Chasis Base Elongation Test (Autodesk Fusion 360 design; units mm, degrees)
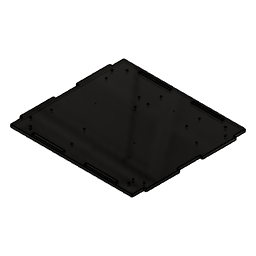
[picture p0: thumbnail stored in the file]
sketch "Sketch1" plane through (0, 0, 0) normal (0, 0, 1) x axis (1, 0, 0)
  line L1 (105, 0) -> (105, 170)
  line L2 (270, 85) -> (105, 85)
  line L3 (187.5, 0) -> (187.5, 170)
  line L4 (270, 170) -> (270, 0)
  line L5 (270, 0) -> (105, 0)
  line L6 (105, 170) -> (270, 170)
  line L7 (214, 237) -> (105, 237)
  line L8 (214, 185) -> (214, 237)
  line L9 (105, 185) -> (214, 185)
  line L10 (105, 237) -> (105, 185)
  line L11 (214, 237) -> (105, 185)
  line L12 (214, 185) -> (105, 237)
  line L13 (110.5, 194.5) -> (208.5, 194.5)
  line L14 (110.5, 227.5) -> (110.5, 194.5)
  line L15 (208.5, 227.5) -> (110.5, 227.5)
  line L16 (208.5, 194.5) -> (208.5, 227.5)
  line L17 (110.5, 227.5) -> (208.5, 194.5)
  line L18 (208.5, 227.5) -> (110.5, 194.5)
  line L19 (159.5, 237) -> (159.5, 185)
  line L20 (0, -15) -> (0, 0)
  line L21 (-15, -15) -> (0, -15)
  line L22 (285, 170) -> (270, 170)
  line L23 (214, 252) -> (214, 237)
  line L24 (285, 252) -> (214, 252)
  line L25 (285, -15) -> (-15, -15)
  line L26 (285, 252) -> (285, -15)
  line L27 (-15, 252) -> (285, 252)
  line L28 (-15, -15) -> (-15, 252)
  line L29 (4.75, 385) -> (24.75, 385)
  line L30 (0, 385) -> (24.75, 385)
  line L31 (11.6375, 396.25) -> (39.75, 396.25)
  line L32 (9.75, 373.75) -> (9.75, 396.25)
  line L33 (39.75, 373.75) -> (11.6375, 373.75)
  line L34 (39.75, 396.25) -> (39.75, 373.75)
  line L35 (9.75, 373.75) -> (39.75, 396.25)
  line L36 (39.75, 373.75) -> (9.75, 396.25)
  line L37 (1.4898, 388.4545) -> (8.3773, 394.9545)
  line L38 (8.3773, 375.0455) -> (1.4898, 381.5455)
  line L39 (-15, -15) -> (285, 252)
  line L40 (285, -15) -> (-15, 252)
  line L41 (-26, 263) -> (296, 263)
  line L42 (-26, -26) -> (-26, 263)
  line L43 (296, -26) -> (-26, -26)
  line L44 (296, 263) -> (296, -26)
  line L45 (-26, -26) -> (296, 263)
  line L46 (296, -26) -> (-26, 263)
  line L47 (15.3041, 394.5767) -> (10.5355, 389.7534)
  line L48 (24.75, 395.23) -> (16.8686, 395.23)
  line L49 (24.75, 374.77) -> (14.3, 374.77)
  line L50 (39.6, 388.2067) -> (39.6, 379.17)
  line L51 (24.75, 374.77) -> (35.2, 374.77)
  line L52 (9.9, 388.2067) -> (9.9, 379.17)
  line L53 (34.1959, 394.5767) -> (38.9645, 389.7534)
  line L54 (24.75, 395.23) -> (32.6314, 395.23)
  line L55 (24.75, 374.77) -> (24.75, 395.23)
  line L56 (9.9, 385) -> (24.75, 385)
  line L57 (39.6, 385) -> (24.75, 385)
  line L58 (108, -15) -> (28, -15)
  line L59 (108, -21) -> (108, -15)
  line L60 (28, -21) -> (108, -21)
  line L61 (28, -15) -> (28, -21)
  line L62 (135, 263) -> (135, -26)
  line L63 (162, -15) -> (242, -15)
  line L64 (242, -21) -> (162, -21)
  line L65 (242, -15) -> (242, -21)
  line L66 (162, -21) -> (162, -15)
  line L67 (296, 118.5) -> (-26, 118.5)
  line L68 (162, 258) -> (162, 252)
  line L69 (242, 258) -> (162, 258)
  line L70 (242, 252) -> (242, 258)
  line L71 (108, 258) -> (108, 252)
  line L72 (28, 258) -> (108, 258)
  line L73 (108, 252) -> (28, 252)
  line L74 (162, 252) -> (242, 252)
  line L75 (28, 252) -> (28, 258)
  line L76 (-20, 4) -> (-20, -26)
  line L77 (-26, 4) -> (-20, 4)
  line L78 (-20, 233) -> (-20, 263)
  line L79 (-26, 233) -> (-20, 233)
  line L80 (-26, 233) -> (-26, 4)
  line L81 (290, 4) -> (290, -26)
  line L82 (296, 4) -> (290, 4)
  line L83 (296, 233) -> (296, 4)
  line L84 (296, 233) -> (290, 233)
  line L85 (290, 233) -> (290, 263)
  line L86 (290, 263) -> (-20, 263)
  line L87 (290, -26) -> (-20, -26)
  line L88 (4.75, 385) -> (44.75, 385)
  line L89 (290, 460) -> (-20, 460)
  line L90 (28, 304) -> (28, 310)
  line L91 (108, 304) -> (28, 304)
  line L92 (108, 310) -> (108, 304)
  line L93 (162, 304) -> (162, 310)
  line L94 (242, 304) -> (162, 304)
  line L95 (242, 310) -> (242, 304)
  line L96 (242, 310) -> (290, 310)
  line L97 (108, 310) -> (162, 310)
  line L98 (28, 310) -> (-20, 310)
  line L99 (-20, 340) -> (-20, 310)
  line L100 (-26, 340) -> (-20, 340)
  line L101 (-26, 430) -> (-26, 340)
  line L102 (-20, 430) -> (-26, 430)
  line L103 (-20, 430) -> (-20, 460)
  line L104 (-20, 385) -> (290, 385)
  line L105 (28, 460) -> (-20, 460)
  line L106 (242, 460) -> (242, 466)
  line L107 (28, 466) -> (28, 460)
  line L108 (242, 466) -> (162, 466)
  line L109 (242, 460) -> (290, 460)
  line L110 (108, 460) -> (108, 466)
  line L111 (108, 460) -> (162, 460)
  line L112 (108, 466) -> (28, 466)
  line L113 (162, 466) -> (162, 460)
  line L114 (135, 460) -> (135, 385)
  line L115 (296, 430) -> (296, 340)
  line L116 (290, 430) -> (290, 460)
  line L117 (290, 340) -> (290, 310)
  line L118 (296, 340) -> (290, 340)
  line L119 (290, 430) -> (296, 430)
  line L120 (0, 412.9257) -> (0, 385)
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  point P9 (105, 0)
  point P32 (105, 0)
  point P31 (105, 85)
  point P30 (270, 85)
  point P28 (187.5, 170)
  point P25 (187.5, 0)
  point P41 (159.5, 211)
  point P39 (110.5, 227.5)
  point P42 (110.5, 227.5)
  point P40 (208.5, 227.5)
  point P43 (208.5, 227.5)
  point P38 (110.5, 194.5)
  point P44 (110.5, 194.5)
  point P37 (208.5, 194.5)
  point P45 (208.5, 194.5)
  point P46 (159.5, 185)
  point P47 (159.5, 237)
  point P61 (4.75, 385)
  point P62 (4.75, 385)
  point P69 (24.75, 385)
  point P60 (24.75, 385)
  point P66 (9.75, 396.25)
  point P67 (9.75, 373.75)
  point P84 (135, 118.5)
  point P107 (24.75, 385)
  point P108 (9.9, 385)
  point P109 (39.6, 385)
  point P110 (28, -15)
  point P114 (135, -26)
  point P115 (135, 263)
  point P116 (242, -15)
  point P111 (108, -15)
  point P117 (162, -15)
  point P112 (108, -21)
  point P118 (162, -21)
  point P113 (28, -21)
  point P119 (242, -21)
  point P120 (-26, 118.5)
  point P121 (296, 118.5)
  point P125 (242, 252)
  point P122 (162, 252)
  point P123 (162, 258)
  point P124 (242, 258)
  point P130 (-20, -26)
  point P132 (-26, 4)
  point P133 (-20, 263)
  point P131 (-20, 4)
  point P134 (-20, 233)
  point P135 (-26, 233)
  point P136 (290, -26)
  point P137 (290, 4)
  point P138 (296, 4)
  point P141 (290, 263)
  point P140 (290, 233)
  point P139 (296, 233)
  point P79 (44.75, 385)
  point P142 (44.75, 385)
  point P143 (4.75, 385)
  point P144 (-20, 310)
  point P170 (-20, 460)
  point P145 (290, 310)
  point P171 (290, 460)
  point P148 (28, 310)
  point P168 (28, 460)
  point P149 (28, 304)
  point P169 (28, 466)
  point P150 (108, 304)
  point P162 (108, 466)
  point P151 (108, 310)
  point P167 (108, 460)
  point P152 (162, 310)
  point P165 (162, 460)
  point P153 (162, 304)
  point P164 (162, 466)
  point P154 (242, 304)
  point P163 (242, 466)
  point P155 (242, 310)
  point P166 (242, 460)
  point P172 (135, 385)
  point P173 (135, 460)
  point P178 (290, 310)
  point P146 (-20, 460)
  point P176 (290, 460)
  point P156 (-20, 340)
  point P179 (290, 340)
  point P157 (-26, 340)
  point P174 (296, 340)
  point P158 (-26, 430)
  point P175 (296, 430)
  point P159 (-20, 430)
  point P177 (290, 430)
  point P180 (0, 385)
  point P203 (-445.6879, 118.6195)
  point P208 (-445.6879, 118.6195)
  point P329 (-3, 53)
  point P332 (-3, 53)
  point P339 (-3, 53)
  point P340 (108, -18)
  point P341 (162, -18)
  point P20 (266, 4)
  point P349 (266, 4)
  point P351 (258, 9)
  point P353 (258, 9)
  point P21 (109, 4)
  point P354 (109, 4)
  point P356 (101, 9)
  point P358 (101, 9)
  point P48 (109, 166)
  point P359 (109, 166)
  point P361 (101, 171)
  point P363 (101, 171)
  point P49 (266, 166)
  point P364 (266, 166)
  point P366 (258, 171)
  point P368 (258, 171)
  point P17 (270, 0)
  point P18 (270, 170)
  point P19 (215, 4)
  point P22 (165, 4)
  point P26 (109, 166)
  point P29 (160, 166)
  point P12 (215, 166)
  point P27 (266, 166)
  point P15 (266, 70)
  point P7 (266, 110)
  point P6 (109, 60)
  point P8 (109, 100)
  point P23 (190, 40)
  point P24 (190, 74)
  point P10 (259, 15)
  point P14 (259, 30)
  point P11 (259, 45)
  point P13 (259, 60)
  point P2 (259, 159)
  point P3 (259, 144)
  point P4 (115, 145)
  point P5 (115, 130)
  point P33 (105, 237)
  point P34 (214, 237)
  point P36 (105, 185)
  point P53 (0, -15)
  point P54 (-15, -15)
  point P55 (285, 170)
  point P56 (214, 252)
  point P63 (0, 385)
  point P68 (39.75, 373.75)
  point P82 (-26, -26)
  point P83 (296, -26)
  point P81 (-26, 263)
  point P59 (-15, 252)
  point P102 (9.9, 379.17)
  point P106 (9.9, 388.2067)
  point P87 (16.8686, 395.23)
  point P99 (24.75, 395.23)
  point P85 (24.75, 374.77)
  point P101 (14.3, 374.77)
  point P183 (-230.6879, -25.8805)
  point P184 (-260.6879, -25.8805)
  point P186 (-260.6879, 3.9615)
  point P187 (-266.6879, 3.9615)
  point P188 (-260.6879, 232.9615)
  point P189 (-266.6879, 232.9615)
  point P185 (-260.6879, 263.1195)
  point P190 (-410.6879, 263.1195)
  point P191 (-410.6879, -25.8805)
  point P200 (-430.6879, -25.8805)
  point P202 (-430.6879, 118.6195)
  point P205 (-458.1879, 58.6195)
  point P206 (-458.1879, 178.6195)
  point P209 (-458.1879, 118.6195)
  point P210 (-478.1879, 118.6195)
  point P213 (-478.1879, 45.3383)
  point P214 (-478.1879, 15.3383)
  point P219 (-260.6879, 252)
  point P220 (-290.6879, 252)
  point P222 (-410.6879, 252)
  point P223 (-380.6879, 252)
  point P224 (-290.6879, 252)
  point P226 (-380.6879, 258)
  point P207 (-433.1879, 178.6195)
  point P182 (-230.6879, 263.1195)
  point P275 (590, 237)
  point P277 (490, 237)
  point P278 (490, 197)
  point P299 (540, 237)
  point P300 (590, 187)
  point P333 (87, 53)
  point P325 (-3, 203)
  point P350 (258, 4)
  point P352 (266, 9)
  point P355 (101, 4)
  point P357 (109, 9)
  point P365 (258, 166)
  point P367 (266, 171)
  horizontal L5
  vertical L4
  horizontal L6
  vertical L1
  coincident P9 P32
  midpoint P31 L1
  midpoint P30 L4
  midpoint P28 L6
  midpoint P25 L5
  horizontal L7
  vertical L8
  horizontal L9
  vertical L10
  horizontal L13
  perpendicular L13 L14
  parallel L13 L15
  parallel L14 L16
  coincident L17 P41
  coincident L18 P41
  midpoint L12 P41
  coincident P39 P42
  coincident P40 P43
  coincident P38 P44
  coincident P37 P45
  midpoint L9 P46
  midpoint L7 P47
  perpendicular L20 L21
  perpendicular L4 L22
  perpendicular L7 L23
  perpendicular L4 L24
  horizontal L25
  vertical L26
  horizontal L27
  vertical L28
  coincident P61 P62
  parallel L29 L30
  horizontal L31
  perpendicular L31 L32
  parallel L31 L33
  parallel L32 L34
  coincident L35 P69
  coincident L36 P69
  coincident P60 P69
  coincident P66 L37
  coincident P66 L31
  coincident P67 L38
  coincident P67 L33
  horizontal L41
  perpendicular L41 L42
  parallel L41 L43
  parallel L42 L44
  coincident L45 P84
  coincident L46 P84
  midpoint L40 P84
  parallel L48 L54
  parallel L51 L54
  parallel L49 L51
  equal L50 L52
  equal L47 L53
  equal L48 L54
  equal L49 L51
  collinear L48 L54
  collinear L49 L51
  perpendicular L49 L55
  midpoint L55 P107
  coincident L52 P108
  perpendicular L52 L56
  coincident L50 P109
  equal L56 L57
  parallel L50 L55
  horizontal L58
  vertical L59
  horizontal L60
  vertical L61
  coincident L25 P110
  midpoint L43 P114
  midpoint L41 P115
  symmetric P110 L62 P116
  symmetric P111 L62 P117
  symmetric P112 L62 P118
  symmetric P113 L62 P119
  midpoint L42 P120
  midpoint L44 P121
  symmetric P116 L67 P125
  symmetric P117 L67 P122
  symmetric P118 L67 P123
  symmetric P119 L67 P124
  coincident L43 P130
  perpendicular L25 L76
  coincident L42 P132
  perpendicular L42 L77
  symmetric L67 P130 P133
  symmetric L67 P131 P134
  symmetric L67 P132 P135
  symmetric L62 P130 P136
  symmetric L62 P131 P137
  symmetric L62 P132 P138
  symmetric L62 P133 P141
  symmetric L62 P134 P140
  symmetric L62 P135 P139
  coincident P79 P142
  coincident P62 P143
  parallel L29 L88
  equal L37 L38
  perpendicular L71 L91
  perpendicular L70 L94
  perpendicular L99 L100
  perpendicular L100 L101
  symmetric P144 L104 P170
  symmetric P145 L104 P171
  symmetric P148 L104 P168
  symmetric P149 L104 P169
  symmetric P150 L104 P162
  symmetric P151 L104 P167
  symmetric P152 L104 P165
  symmetric P153 L104 P164
  symmetric P154 L104 P163
  symmetric P155 L104 P166
  midpoint L104 P172
  midpoint L111 P173
  symmetric P144 L114 P178
  symmetric P146 L114 P176
  symmetric P156 L114 P179
  symmetric P157 L114 P174
  symmetric P158 L114 P175
  symmetric P159 L114 P177
  coincident L104 P180
  perpendicular L104 L120
  coincident P203 P208
  coincident P329 P332
  coincident P329 P339
  collinear L1 L10
  midpoint L59 P340
  midpoint L66 P341
  coincident P20 P349
  coincident P351 P353
  coincident P21 P354
  coincident P356 P358
  coincident P48 P359
  coincident P361 P363
  coincident P49 P364
  coincident P366 P368
  dimension "d10" distance P17 P18 = 170
  dimension "d11" distance P17 P32 = 165
  dimension "d12" diameter = 3
  dimension "d13" distance P20 L5 = 4
  dimension "d14" distance P20 L4 = 4
  dimension "d15" diameter = 3
  dimension "d16" distance P19 P20 = 51
  dimension "d17" diameter = 3
  dimension "d18" distance P19 P22 = 50
  dimension "d19" diameter = 3
  dimension "d20" distance P21 P22 = 56
  dimension "d21" distance P19 L5 = 4
  dimension "d22" distance P22 L5 = 4
  dimension "d23" distance P21 L5 = 4
  dimension "d24" distance P26 P29 = 51
  dimension "d25" diameter = 3
  dimension "d26" distance P12 P27 = 51
  dimension "d27" diameter = 3
  dimension "d28" distance P15 P20 = 66
  dimension "d29" diameter = 3
  dimension "d30" distance P7 P15 = 40
  dimension "d31" diameter = 3
  dimension "d32" distance P6 P21 = 56
  dimension "d33" diameter = 3
  dimension "d34" distance P6 P8 = 40
  dimension "d35" diameter = 3
  dimension "d36" distance P23 L4 = 80
  dimension "d37" distance P23 L5 = 40
  dimension "d38" diameter = 3
  dimension "d39" distance P23 P24 = 34
  dimension "d40" diameter = 6
  dimension "d41" distance P10 L5 = 15
  dimension "d42" distance P10 L4 = 11
  dimension "d43" diameter = 6
  dimension "d44" diameter = 6
  dimension "d45" diameter = 6
  dimension "d46" distance P10 P14 = 15
  dimension "d47" distance P11 P14 = 15
  dimension "d48" distance P11 P13 = 15
  dimension "d49" diameter = 6
  dimension "d50" distance P2 L6 = 11
  dimension "d51" distance P2 L4 = 11
  dimension "d52" diameter = 6
  dimension "d53" distance P2 P3 = 15
  dimension "d54" diameter = 6
  dimension "d55" distance P4 L6 = 25
  dimension "d56" distance P4 L1 = 10
  dimension "d57" diameter = 6
  dimension "d58" distance P4 P5 = 15
  dimension "d59" distance P33 P34 = 109
  dimension "d60" distance P33 P36 = 52
  dimension "d61" distance P39 P40 = 98
  dimension "d62" distance P38 P39 = 33
  dimension "d63" diameter = 3.5
  dimension "d64" diameter = 3.5
  dimension "d65" diameter = 3.5
  dimension "d66" diameter = 3.5
  dimension "d74" diameter = 3.5
  dimension "d75" diameter = 3.5
  dimension "d76" diameter = 3.5
  dimension "d77" diameter = 3.5
  dimension "d78" distance L6 L9 = 15
  dimension "d81" distance P53 P54 = 15
  dimension "d82" distance P18 P55 = 15
  dimension "d83" distance P34 P56 = 15
  dimension "d86" distance P60 P61 = 20
  dimension "d87" diameter = 4
  dimension "d88" distance P60 P63 = 24.75 (= "( 49.5 / 2 ) * 1 mm")
  dimension "d89" distance P67 P68 = 30
  dimension "d90" distance P66 P67 = 22.5
  dimension "d91" radius = 4.75 (= "( 9.5 / 2 ) * 1 mm")
  dimension "d94" radius = 4.75 (= "( 9.5 / 2 ) * 1 mm")
  dimension "d98" distance P82 P83 = 322
  dimension "d99" distance P81 P82 = 289 (= "267 mm + ( 11 * 2 ) * 1 mm")
  dimension "d100" distance P54 P59 = 267
  dimension "d144" radius = 2.2
  dimension "d145" radius = 4.4
  dimension "d146" distance L48 L49 = 20.46
  dimension "d147" distance P102 P106 = 9.0367
  dimension "d148" distance L50 L52 = 29.7
  dimension "d149" distance P87 P99 = 7.8814
  dimension "d150" distance P85 P101 = 10.45
  dimension "d151" distance L31 L54 = 1.02
  dimension "d152" distance P62 L52 = 5.15
  dimension "d154" distance P110 P111 = 80
  dimension "d155" distance P110 P113 = 6
  dimension "d156" distance L42 L61 = 54
  dimension "d157" distance L28 L42 = 11
  dimension "d158" distance P130 P131 = 30
  dimension "d159" distance L42 L76 = 6
  dimension "d161" distance P62 P79 = 40
  dimension "d162" distance P144 P146 = 150
  dimension "d163" distance P148 P149 = 6
  dimension "d164" distance P144 P156 = 30
  dimension "d165" distance P156 P157 = 6
  dimension "d167" distance P157 P158 = 90
  dimension "d168" distance P183 P184 = 30
  dimension "d169" distance P186 P187 = 6
  dimension "d170" distance P188 P189 = 6
  dimension "d171" distance P185 P190 = 150
  dimension "d172" distance P191 P200 = 20
  dimension "d173" distance P202 P203 = 15
  dimension "d174" distance P205 P206 = 120
  dimension "d175" distance P209 P210 = 20
  dimension "d176" distance P213 P214 = 30
  dimension "d177" distance P219 P220 = 30
  dimension "d178" distance P222 P223 = 30
  dimension "d179" distance P223 P224 = 90
  dimension "d180" distance P223 P226 = 6
  dimension "d181" distance P206 P207 = 25
  dimension "d184" distance P182 P183 = 289
  dimension "d185" distance P275 P277 = 100
  dimension "d186" distance P277 P278 = 40
  dimension "d187" distance P275 P299 = 50
  dimension "d188" distance P275 P300 = 50
  dimension "d189" diameter = 3.5
  dimension "d190" distance = 3
  dimension "d191" distance = 3
  dimension "d192" diameter = 3.5
  dimension "d193" distance = 4
  dimension "d194" distance P329 P333 = 90
  dimension "d195" distance P325 P329 = 150
  dimension "d196" radius = 5
  dimension "d197" radius = 5
  dimension "d198" radius = 5
  dimension "d199" radius = 5
  dimension "d200" diameter = 3
  dimension "d201" distance = 5
  dimension "d202" distance = 3
  dimension "d203" diameter = 3.5
  dimension "d204" diameter = 3.5
  dimension "d205" diameter = 3.5
  dimension "d206" diameter = 3.5
  dimension "d207" distance = 60
  dimension "d208" distance = 23
  dimension "d212" diameter = 3.05
  dimension "d213" diameter = 3.05
  dimension "d214" diameter = 3.05
  dimension "d236" distance P349 P350 = 8
  dimension "d237" distance P349 P352 = 5
  dimension "d238" diameter = 3.5
  dimension "d239" distance P354 P355 = 8
  dimension "d240" distance P354 P357 = 5
  dimension "d241" diameter = 3.5
  dimension "d242" diameter = 3.5
  dimension "d243" distance P364 P365 = 8
  dimension "d244" distance P364 P367 = 5
  dimension "d245" diameter = 3.5
extrude "Extrude1" new body sketch "Sketch1" along normal blind 6
sketch "Sketch3" plane through (0, 0, 6) normal (0, 0, 1) x axis (-1, 0, 0)
  line L1 (-296, -4) -> (-290, -4)
  line L2 (-296, -233) -> (-296, -4)
  line L3 (-290, -233) -> (-296, -233)
  line L4 (-290, -263) -> (-290, -233)
  line L5 (20, -263) -> (-290, -263)
  line L6 (20, -233) -> (20, -263)
  line L7 (26, -233) -> (20, -233)
  line L8 (26, -4) -> (26, -233)
  line L9 (20, -4) -> (26, -4)
  line L10 (20, 26) -> (20, -4)
  line L11 (-290, 26) -> (20, 26)
  line L12 (-290, -4) -> (-290, 26)
  line L13 (-242, -252) -> (-242, -258)
  line L14 (-162, -252) -> (-242, -252)
  line L15 (-162, -258) -> (-162, -252)
  line L16 (-242, -258) -> (-162, -258)
  line L17 (-28, -258) -> (-28, -252)
  line L18 (-108, -258) -> (-28, -258)
  line L19 (-108, -252) -> (-108, -258)
  line L20 (-28, -252) -> (-108, -252)
  line L21 (-28, 21) -> (-108, 21)
  line L22 (-28, 15) -> (-28, 21)
  line L23 (-108, 15) -> (-28, 15)
  line L24 (-108, 21) -> (-108, 15)
  line L25 (-162, 15) -> (-162, 21)
  line L26 (-242, 15) -> (-162, 15)
  line L27 (-242, 21) -> (-242, 15)
  line L28 (-162, 21) -> (-242, 21)
  line L29 (-296, -148) -> (-296, -233)
  line L30 (-296, -89) -> (-296, -4)
  line L31 (-290, -89) -> (-296, -89)
  line L32 (-290, -148) -> (-296, -148)
  line L33 (-290, -148) -> (-290, -89)
  line L34 (-296, -89) -> (-296, -148)
  line L35 (-135, -29) -> (-135, 18)
  line L36 (26, -89) -> (26, -148)
  line L37 (20, -148) -> (20, -89)
  line L38 (20, -89) -> (26, -89)
  line L39 (20, -148) -> (26, -148)
  circle C1 centre (-208.5, -227.5) radius 1.75
  circle C2 centre (-110.5, -227.5) radius 1.75
  circle C3 centre (-208.5, -194.5) radius 1.75
  circle C4 centre (0, -58) radius 1.75
  circle C5 centre (0, -198) radius 1.75
  circle C6 centre (-84, -58) radius 1.75
  circle C7 centre (-84, -198) radius 1.75
  circle C8 centre (-110.5, -194.5) radius 1.75
  circle C9 centre (-258, -9) radius 1.75
  circle C10 centre (-101, -9) radius 1.75
  circle C11 centre (-101, -171) radius 1.75
  circle C12 centre (-258, -171) radius 1.75
  point P5 (-296, -233)
  point P44 (-296, -233)
  point P3 (-296, -4)
  point P46 (-296, -4)
  point P45 (-296, -148)
  point P52 (26, -148)
  point P47 (-296, -89)
  point P53 (26, -89)
  point P48 (-290, -89)
  point P54 (20, -89)
  point P49 (-290, -148)
  point P55 (20, -148)
  coincident P5 P44
  perpendicular L3 L29
  coincident P3 P46
  perpendicular L1 L30
  perpendicular L30 L31
  vertical L35
  symmetric P45 L35 P52
  symmetric P47 L35 P53
  symmetric P48 L35 P54
  symmetric P49 L35 P55
  dimension "d223" distance P44 P45 = 85
  dimension "d224" distance P46 P47 = 85
  dimension "d225" distance P47 P48 = 6
  dimension "d226" distance P45 P49 = 6
extrude "Extrude3" cut sketch "Sketch3" profile of L2 L8 L31 L32 L33 L34 L36 L37 L38 L39 against normal blind 30
sketch "Sketch4" plane through (0, 0, 6) normal (0, 0, 1) x axis (-1, 0, 0)
  line L1 (-296, -148) -> (-290, -148)
  line L2 (-296, -233) -> (-296, -148)
  line L3 (-290, -233) -> (-296, -233)
  line L4 (-290, -263) -> (-290, -233)
  line L5 (20, -263) -> (-290, -263)
  line L6 (20, -233) -> (20, -263)
  line L7 (26, -233) -> (20, -233)
  line L8 (26, -148) -> (26, -233)
  line L9 (20, -148) -> (26, -148)
  line L10 (20, -89) -> (20, -148)
  line L11 (26, -89) -> (20, -89)
  line L12 (26, -4) -> (26, -89)
  line L13 (20, -4) -> (26, -4)
  line L14 (20, 26) -> (20, -4)
  line L15 (-290, 26) -> (20, 26)
  line L16 (-290, -4) -> (-290, 26)
  line L17 (-296, -4) -> (-290, -4)
  line L18 (-296, -89) -> (-296, -4)
  line L19 (-290, -89) -> (-296, -89)
  line L20 (-290, -148) -> (-290, -89)
  line L21 (-242, -252) -> (-242, -258)
  line L22 (-162, -252) -> (-242, -252)
  line L23 (-162, -258) -> (-162, -252)
  line L24 (-242, -258) -> (-162, -258)
  line L25 (-28, -258) -> (-28, -252)
  line L26 (-108, -258) -> (-28, -258)
  line L27 (-108, -252) -> (-108, -258)
  line L28 (-28, -252) -> (-108, -252)
  line L29 (-28, 21) -> (-108, 21)
  line L30 (-28, 15) -> (-28, 21)
  line L31 (-108, 15) -> (-28, 15)
  line L32 (-108, 21) -> (-108, 15)
  line L33 (-162, 15) -> (-162, 21)
  line L34 (-242, 15) -> (-162, 15)
  line L35 (-242, 21) -> (-242, 15)
  line L36 (-162, 21) -> (-242, 21)
  line L37 (20, 15) -> (-28, 15)
  line L38 (10, 15) -> (20, 15)
  line L39 (10, -14.5) -> (10, 15)
  line L40 (20, -14.5) -> (10, -14.5)
  line L41 (20, 15) -> (20, -14.5)
  line L42 (-135, -263) -> (-135, 26)
  line L43 (-290, -118.5) -> (20, -118.5)
  line L44 (-9.5, 15) -> (20, 15)
  line L45 (-9.5, 5) -> (-9.5, 15)
  line L46 (20, 5) -> (-9.5, 5)
  line L47 (20, 15) -> (20, 5)
  circle C1 centre (-208.5, -227.5) radius 1.75
  circle C2 centre (-110.5, -227.5) radius 1.75
  circle C3 centre (-208.5, -194.5) radius 1.75
  circle C4 centre (0, -58) radius 1.75
  circle C5 centre (0, -198) radius 1.75
  circle C6 centre (-84, -58) radius 1.75
  circle C7 centre (-84, -198) radius 1.75
  circle C8 centre (-110.5, -194.5) radius 1.75
  circle C9 centre (10, -14.5) radius 2.05
  circle C10 centre (-280, -14.5) radius 2.05
  circle C11 centre (-280, -222.5) radius 2.05
  circle C12 centre (10, -222.5) radius 2.05
  circle C13 centre (-9.5, 5) radius 2.05
  circle C14 centre (-260.5, 5) radius 2.05
  circle C15 centre (-9.5, -242) radius 2.05
  circle C16 centre (-260.5, -242) radius 2.05
  circle C17 centre (-258, -9) radius 1.75
  circle C18 centre (-101, -9) radius 1.75
  circle C19 centre (-101, -171) radius 1.75
  circle C20 centre (-258, -171) radius 1.75
  point P39 (-28, 15)
  point P46 (-28, 15)
  point P47 (20, 15)
  point P49 (10, -14.5)
  point P51 (10, -14.5)
  point P52 (-135, 26)
  point P53 (-135, -263)
  point P54 (20, -118.5)
  point P55 (-290, -118.5)
  point P60 (-9.5, 5)
  point P62 (-9.5, 5)
  point P48 (10, 15)
  point P50 (20, -14.5)
  point P59 (-9.5, 15)
  point P61 (20, 5)
  coincident P39 P46
  coincident L14 P47
  perpendicular L14 L37
  horizontal L38
  vertical L39
  horizontal L40
  vertical L41
  coincident P49 P51
  midpoint L15 P52
  midpoint L5 P53
  midpoint L10 P54
  midpoint L20 P55
  symmetric C9 L42 C10
  symmetric C9 L43 C12
  symmetric L43 C10 C11
  horizontal L44
  vertical L45
  horizontal L46
  vertical L47
  coincident P60 P62
  symmetric L42 C13 C14
  symmetric L43 C13 C15
  symmetric L43 C14 C16
  dimension "d229" distance P47 P48 = 10
  dimension "d230" distance P47 P50 = 29.5 (= "27 mm + 2.5 mm")
  dimension "d231" diameter C9 = 4.1
  dimension "d233" distance P47 P59 = 29.5
  dimension "d234" distance P47 P61 = 10
  dimension "d235" diameter C13 = 4.1
extrude "Extrude4" cut sketch "Sketch4" profile of C9 C10 C11 C12 C13 C14 C15 C16 no distance stored
sketch "Sketch5" plane through (0, 0, 6) normal (0, 0, 1) x axis (-1, 0, 0)
  line L1 (-296, -148) -> (-290, -148)
  line L2 (-296, -233) -> (-296, -148)
  line L3 (-290, -233) -> (-296, -233)
  line L4 (-290, -263) -> (-290, -233)
  line L5 (20, -263) -> (-290, -263)
  line L6 (20, -233) -> (20, -263)
  line L7 (26, -233) -> (20, -233)
  line L8 (26, -148) -> (26, -233)
  line L9 (20, -148) -> (26, -148)
  line L10 (20, -89) -> (20, -148)
  line L11 (26, -89) -> (20, -89)
  line L12 (26, -4) -> (26, -89)
  line L13 (20, -4) -> (26, -4)
  line L14 (20, 26) -> (20, -4)
  line L15 (-290, 26) -> (20, 26)
  line L16 (-290, -4) -> (-290, 26)
  line L17 (-296, -4) -> (-290, -4)
  line L18 (-296, -89) -> (-296, -4)
  line L19 (-290, -89) -> (-296, -89)
  line L20 (-290, -148) -> (-290, -89)
  line L21 (-242, -252) -> (-242, -258)
  line L22 (-162, -252) -> (-242, -252)
  line L23 (-162, -258) -> (-162, -252)
  line L24 (-242, -258) -> (-162, -258)
  line L25 (-162, 15) -> (-162, 21)
  line L26 (-242, 15) -> (-162, 15)
  line L27 (-242, 21) -> (-242, 15)
  line L28 (-162, 21) -> (-242, 21)
  line L29 (-28, 21) -> (-108, 21)
  line L30 (-28, 15) -> (-28, 21)
  line L31 (-108, 15) -> (-28, 15)
  line L32 (-108, 21) -> (-108, 15)
  line L33 (-28, -258) -> (-28, -252)
  line L34 (-108, -258) -> (-28, -258)
  line L35 (-108, -252) -> (-108, -258)
  line L36 (-28, -252) -> (-108, -252)
  line L37 (-84, -198) -> (0, -58)
  line L38 (-84, -58) -> (0, -198)
  line L39 (-208.5, -194.5) -> (-110.5, -227.5)
  line L40 (-208.5, -227.5) -> (-110.5, -194.5)
  line L41 (-101, -9) -> (-258, -171)
  line L42 (-258, -9) -> (-101, -171)
  circle C1 centre (-260.5, 5) radius 2.05
  circle C2 centre (-280, -14.5) radius 2.05
  circle C3 centre (-280, -222.5) radius 2.05
  circle C4 centre (-260.5, -242) radius 2.05
  circle C5 centre (-9.5, 5) radius 2.05
  circle C6 centre (10, -14.5) radius 2.05
  circle C7 centre (10, -222.5) radius 2.05
  circle C8 centre (-9.5, -242) radius 2.05
  circle C9 centre (-84, -198) radius 1.75
  circle C10 centre (-258, -9) radius 1.75
  circle C11 centre (-101, -9) radius 1.75
  circle C12 centre (-101, -171) radius 1.75
  circle C13 centre (-258, -171) radius 1.75
  circle C14 centre (-110.5, -227.5) radius 1.75
  circle C15 centre (-208.5, -194.5) radius 1.75
  circle C16 centre (-110.5, -194.5) radius 1.75
  circle C17 centre (0, -198) radius 1.75
  circle C18 centre (-84, -58) radius 1.75
  circle C19 centre (0, -58) radius 1.75
  circle C20 centre (-208.5, -227.5) radius 1.75
  circle C21 centre (-42, -128) radius 0.5
  circle C22 centre (-159.5, -211) radius 0.5
  circle C23 centre (-179.5, -90) radius 0.5
  point P56 (0, -58)
  point P58 (0, -58)
  point P30 (-84, -198)
  point P59 (-84, -198)
  point P54 (0, -198)
  point P60 (0, -198)
  point P55 (-84, -58)
  point P61 (-84, -58)
  point P39 (-110.5, -227.5)
  point P62 (-110.5, -227.5)
  point P44 (-208.5, -194.5)
  point P63 (-208.5, -194.5)
  point P49 (-110.5, -194.5)
  point P64 (-110.5, -194.5)
  point P57 (-208.5, -227.5)
  point P65 (-208.5, -227.5)
  point P34 (-258, -171)
  point P66 (-258, -171)
  point P32 (-101, -9)
  point P67 (-101, -9)
  point P33 (-101, -171)
  point P68 (-101, -171)
  point P31 (-258, -9)
  point P69 (-258, -9)
  point P70 (-42, -128)
  point P71 (-159.5, -211)
  point P72 (-179.5, -90)
  coincident P56 P58
  coincident P30 P59
  coincident P54 P60
  coincident P55 P61
  coincident P39 P62
  coincident P44 P63
  coincident P49 P64
  coincident P57 P65
  coincident P34 P66
  coincident P32 P67
  coincident P33 P68
  coincident P31 P69
  midpoint L38 P70
  midpoint L39 P71
  midpoint L41 P72
  dimension "d246" diameter C21 = 1
  dimension "d247" diameter C22 = 1 (= "d246")
  dimension "d248" diameter C23 = 1 (= "d246")
extrude "Extrude5" add sketch "Sketch5" profile of C21 C22 C23 along normal blind 0.1
sketch "Sketch6" plane through (0, 0, 0) normal (0, 0, -1) x axis (1, 0, 0)
  line L1 (290, -148) -> (296, -148)
  line L2 (290, -89) -> (290, -148)
  line L3 (296, -89) -> (290, -89)
  line L4 (296, -4) -> (296, -89)
  line L5 (290, -4) -> (296, -4)
  line L6 (290, 26) -> (290, -4)
  line L7 (-20, 26) -> (290, 26)
  line L8 (-20, -4) -> (-20, 26)
  line L9 (-26, -4) -> (-20, -4)
  line L10 (-26, -89) -> (-26, -4)
  line L11 (-20, -89) -> (-26, -89)
  line L12 (-20, -148) -> (-20, -89)
  line L13 (-26, -148) -> (-20, -148)
  line L14 (-26, -233) -> (-26, -148)
  line L15 (-20, -233) -> (-26, -233)
  line L16 (-20, -263) -> (-20, -233)
  line L17 (290, -263) -> (-20, -263)
  line L18 (290, -233) -> (290, -263)
  line L19 (296, -233) -> (290, -233)
  line L20 (296, -148) -> (296, -233)
  line L21 (28, -252) -> (28, -258)
  line L22 (108, -252) -> (28, -252)
  line L23 (108, -258) -> (108, -252)
  line L24 (28, -258) -> (108, -258)
  line L25 (108, 21) -> (28, 21)
  line L26 (108, 15) -> (108, 21)
  line L27 (28, 15) -> (108, 15)
  line L28 (28, 21) -> (28, 15)
  line L29 (162, 21) -> (162, 15)
  line L30 (242, 21) -> (162, 21)
  line L31 (242, 15) -> (242, 21)
  line L32 (162, 15) -> (242, 15)
  line L33 (242, -258) -> (242, -252)
  line L34 (162, -258) -> (242, -258)
  line L35 (162, -252) -> (162, -258)
  line L36 (242, -252) -> (162, -252)
  line L37 (-26, -4) -> (-20, -4)
  line L38 (-26, -89) -> (-26, -4)
  line L39 (-20, -89) -> (-26, -89)
  line L40 (-20, -4) -> (-20, -89)
  line L41 (-26, -148) -> (-20, -148)
  line L42 (-26, -233) -> (-26, -148)
  line L43 (-20, -233) -> (-26, -233)
  line L44 (-20, -148) -> (-20, -233)
  line L45 (290, -233) -> (296, -233)
  line L46 (290, -148) -> (290, -233)
  line L47 (296, -148) -> (290, -148)
  line L48 (296, -233) -> (296, -148)
  line L49 (290, -89) -> (296, -89)
  line L50 (290, -4) -> (290, -89)
  line L51 (296, -4) -> (290, -4)
  line L52 (296, -89) -> (296, -4)
  circle C1 centre (260.5, 5) radius 2.05
  circle C2 centre (280, -14.5) radius 2.05
  circle C3 centre (280, -222.5) radius 2.05
  circle C4 centre (260.5, -242) radius 2.05
  circle C5 centre (9.5, 5) radius 2.05
  circle C6 centre (-10, -14.5) radius 2.05
  circle C7 centre (-10, -222.5) radius 2.05
  circle C8 centre (9.5, -242) radius 2.05
  circle C9 centre (208.5, -227.5) radius 1.75
  circle C10 centre (0, -58) radius 1.75
  circle C11 centre (84, -58) radius 1.75
  circle C12 centre (0, -198) radius 1.75
  circle C13 centre (110.5, -194.5) radius 1.75
  circle C14 centre (208.5, -194.5) radius 1.75
  circle C15 centre (110.5, -227.5) radius 1.75
  circle C16 centre (258, -171) radius 1.75
  circle C17 centre (101, -171) radius 1.75
  circle C18 centre (101, -9) radius 1.75
  circle C19 centre (258, -9) radius 1.75
  circle C20 centre (84, -198) radius 1.75
  point P20 (-26, -89)
  point P60 (-26, -89)
  point P18 (-20, -4)
  point P58 (-20, -4)
  point P24 (-26, -233)
  point P64 (-26, -233)
  point P22 (-20, -148)
  point P62 (-20, -148)
  point P11 (290, -148)
  point P68 (290, -148)
  point P29 (296, -233)
  point P66 (296, -233)
  point P15 (290, -4)
  point P72 (290, -4)
  point P13 (296, -89)
  point P70 (296, -89)
  horizontal L37
  vertical L38
  horizontal L39
  vertical L40
  coincident P20 P60
  coincident P18 P58
  horizontal L41
  vertical L42
  horizontal L43
  vertical L44
  coincident P24 P64
  coincident P22 P62
  horizontal L45
  vertical L46
  horizontal L47
  vertical L48
  coincident P11 P68
  coincident P29 P66
  horizontal L49
  vertical L50
  horizontal L51
  vertical L52
  coincident P15 P72
  coincident P13 P70
extrude "Extrude6" add sketch "Sketch6" profile of L1 L3 L4 L5 L9 L10 L11 L13 L14 L15 L19 L20 L37 L38 L39 L40 L41 L42 L43 L44 L45 L46 L47 L48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 along normal blind 0.1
